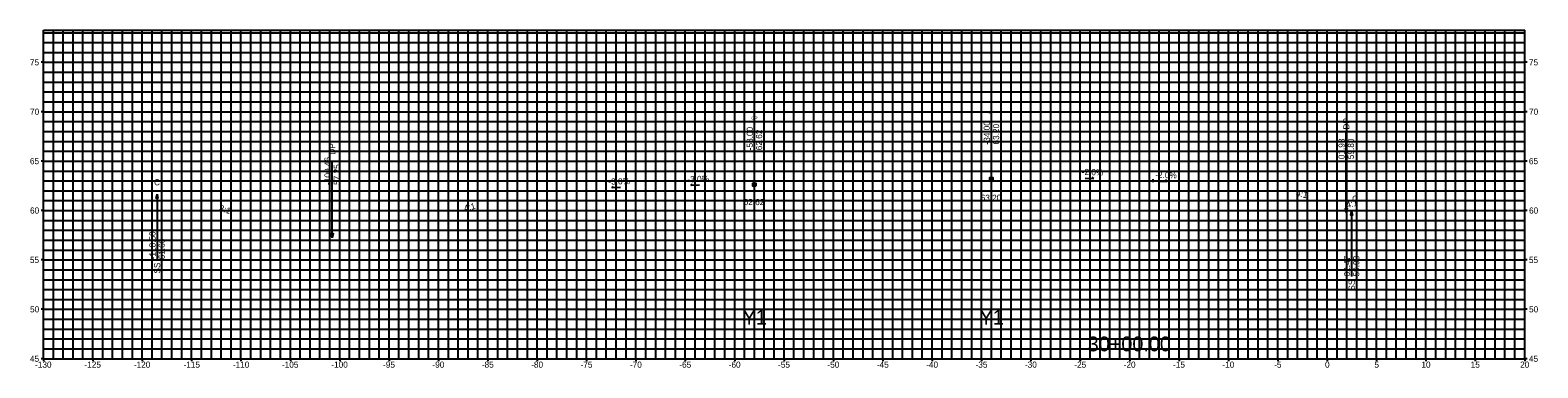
# Model space of a CAD drawing. Extents: x -111 to 41, y 44 to 78.
import ezdxf

# ---------------------------------------------------------------- set-up
doc = ezdxf.new("R2010")
doc.units = 0
for name, color, linetype in [('P_NCDOT_XS_Label_Grade_Point', 7, 'Continuous'), ('P_NCDOT_XS_Label_Grading_Side_Slope', 7, 'Continuous'), ('P_NCDOT_XS_Leader_Line', 7, 'Continuous'), ('P_NCDOT_XS_Sheet_Alignment_Station_Label', 7, 'Continuous'), ('P_NCDOT_XS_Sheet_Grid_Border', 7, 'Continuous'), ('P_NCDOT_XS_Slope_Label', 7, 'Continuous'), ('Sheet_Cross_Section_Scale_CELL', 7, 'Continuous'), ('Sheet_Grid_Middle', 7, 'Continuous'), ('Sheet_Grid_Minor', 7, 'Continuous'), ('Sheet_Named_Boundary', 7, 'Continuous'), ('Sheet_Plan_CELL', 7, 'Continuous'), ('Sheet_RDY_XS_Number', 7, 'Continuous'), ('Sheet_RDY_XS_Project_Number', 7, 'Continuous'), ('z - Construction', 7, 'Continuous')]:
    doc.layers.add(name, color=color, linetype=linetype)

msp = doc.modelspace()

# ---------------------------------------------------------------- linework, layer by layer
at = {"layer": 'P_NCDOT_XS_Label_Grading_Side_Slope'}
for p, q in [((-44.45, 62.54), (-44.28, 62.67)), ((-4.52, 63.27), (-3.62, 63.25)), ((-3.62, 63.25), (-3.79, 63.38)), ((2.91, 62.98), (3.81, 62.96)), ((3.81, 62.96), (3.64, 63.08)), ((-52.45, 62.3), (-52.28, 62.43)), ((-51.55, 62.33), (-52.45, 62.3)), ((-43.55, 62.57), (-44.45, 62.54))]:
    msp.add_line(p, q, dxfattribs=at)
at = {"layer": 'P_NCDOT_XS_Sheet_Alignment_Station_Label'}
for p, q in [((-38, 62.62), (-38, 68.86)), ((-14, 63.2), (-14, 69.44)), ((21.93, 59.8), (21.93, 67.9)), ((21.93, 59.8), (21.93, 67.6)), ((-80.76, 57.25), (-80.76, 65.05)), ((-98.5, 61.66), (-98.5, 55.06)), ((22.47, 59.93), (22.47, 53.33))]:
    msp.add_line(p, q, dxfattribs=at)
for points in [[(-37.85, 62.47), (-38.15, 62.47), (-38.15, 62.77), (-37.85, 62.77)], [(-13.85, 63.05), (-14.15, 63.05), (-14.15, 63.35), (-13.85, 63.35)], [(-98.5, 61.66), (-98.41, 61.25), (-98.58, 61.25)], [(21.93, 59.8), (21.84, 60.21), (22.01, 60.21)], [(21.93, 59.8), (21.85, 60.21), (22.02, 60.21)], [(22.47, 59.93), (22.56, 59.52), (22.39, 59.52)], [(-80.76, 57.25), (-80.85, 57.66), (-80.67, 57.66)]]:
    msp.add_lwpolyline(points, close=True, dxfattribs=at)
at = {"layer": 'Sheet_Grid_Middle'}
for p, q in [((2.36, 62.87), (2.36, 63.18)), ((-50, 62.26), (-50, 62.57))]:
    msp.add_line(p, q, dxfattribs=at)
at = {"layer": 'Sheet_Named_Boundary'}
for p, q in [((-110, 78.26), (40, 78.26)), ((-110, 45), (-110, 78.26)), ((40, 45), (40, 78.26)), ((-110, 45), (40, 45))]:
    msp.add_line(p, q, dxfattribs=at)
at = {"layer": 'Sheet_Plan_CELL'}
for p, q in [((-110, 78), (40, 78)), ((-109, 45), (-109, 78.26)), ((-108, 45), (-108, 78.26)), ((-107, 45), (-107, 78.26)), ((-106, 45), (-106, 78.26)), ((-104, 45), (-104, 78.26)), ((-103, 45), (-103, 78.26)), ((-102, 45), (-102, 78.26)), ((-101, 45), (-101, 78.26)), ((-99, 45), (-99, 78.26)), ((-98, 45), (-98, 78.26)), ((-97, 45), (-97, 78.26)), ((-96, 45), (-96, 78.26)), ((-94, 45), (-94, 78.26)), ((-93, 45), (-93, 78.26)), ((-92, 45), (-92, 78.26)), ((-91, 45), (-91, 78.26)), ((-89, 45), (-89, 78.26)), ((-88, 45), (-88, 78.26)), ((-87, 45), (-87, 78.26)), ((-86, 45), (-86, 78.26)), ((-84, 45), (-84, 78.26)), ((-83, 45), (-83, 78.26)), ((-82, 45), (-82, 78.26)), ((-81, 45), (-81, 78.26)), ((-79, 45), (-79, 78.26)), ((-78, 45), (-78, 78.26)), ((-77, 45), (-77, 78.26)), ((-76, 45), (-76, 78.26)), ((-74, 45), (-74, 78.26)), ((-73, 45), (-73, 78.26)), ((-72, 45), (-72, 78.26)), ((-71, 45), (-71, 78.26)), ((-69, 45), (-69, 78.26)), ((-68, 45), (-68, 78.26)), ((-67, 45), (-67, 78.26)), ((-66, 45), (-66, 78.26)), ((-64, 45), (-64, 78.26)), ((-63, 45), (-63, 78.26)), ((-62, 45), (-62, 78.26)), ((-61, 45), (-61, 78.26)), ((-59, 45), (-59, 78.26)), ((-58, 45), (-58, 78.26)), ((-57, 45), (-57, 78.26)), ((-56, 45), (-56, 78.26)), ((-54, 45), (-54, 78.26)), ((-53, 45), (-53, 78.26)), ((-52, 45), (-52, 78.26)), ((-51, 45), (-51, 78.26)), ((-49, 45), (-49, 78.26)), ((-48, 45), (-48, 78.26)), ((-47, 45), (-47, 78.26)), ((-46, 45), (-46, 78.26)), ((-44, 45), (-44, 78.26)), ((-43, 45), (-43, 78.26)), ((-42, 45), (-42, 78.26)), ((-41, 45), (-41, 78.26)), ((-39, 45), (-39, 78.26)), ((-38, 45), (-38, 78.26)), ((-37, 45), (-37, 78.26)), ((-36, 45), (-36, 78.26)), ((-34, 45), (-34, 78.26)), ((-33, 45), (-33, 78.26)), ((-32, 45), (-32, 78.26)), ((-31, 45), (-31, 78.26)), ((-29, 45), (-29, 78.26)), ((-28, 45), (-28, 78.26)), ((-27, 45), (-27, 78.26)), ((-26, 45), (-26, 78.26)), ((-24, 45), (-24, 78.26)), ((-23, 45), (-23, 78.26)), ((-22, 45), (-22, 78.26)), ((-21, 45), (-21, 78.26)), ((-19, 45), (-19, 78.26)), ((-18, 45), (-18, 78.26)), ((-17, 45), (-17, 78.26)), ((-16, 45), (-16, 78.26)), ((-14, 45), (-14, 78.26)), ((-13, 45), (-13, 78.26)), ((-12, 45), (-12, 78.26)), ((-11, 45), (-11, 78.26)), ((-9, 45), (-9, 78.26)), ((-8, 45), (-8, 78.26)), ((-7, 45), (-7, 78.26)), ((-6, 45), (-6, 78.26)), ((-4, 45), (-4, 78.26)), ((-3, 45), (-3, 78.26)), ((-2, 45), (-2, 78.26)), ((-1, 45), (-1, 78.26)), ((1, 45), (1, 78.26)), ((2, 45), (2, 78.26)), ((3, 45), (3, 78.26)), ((4, 45), (4, 78.26)), ((6, 45), (6, 78.26)), ((7, 45), (7, 78.26)), ((8, 45), (8, 78.26)), ((9, 45), (9, 78.26)), ((11, 45), (11, 78.26)), ((12, 45), (12, 78.26)), ((13, 45), (13, 78.26)), ((14, 45), (14, 78.26)), ((16, 45), (16, 78.26)), ((17, 45), (17, 78.26)), ((18, 45), (18, 78.26)), ((19, 45), (19, 78.26)), ((21, 45), (21, 78.26)), ((22, 45), (22, 78.26)), ((23, 45), (23, 78.26)), ((24, 45), (24, 78.26)), ((26, 45), (26, 78.26)), ((27, 45), (27, 78.26)), ((28, 45), (28, 78.26)), ((29, 45), (29, 78.26)), ((31, 45), (31, 78.26)), ((32, 45), (32, 78.26)), ((33, 45), (33, 78.26)), ((34, 45), (34, 78.26)), ((36, 45), (36, 78.26)), ((37, 45), (37, 78.26)), ((38, 45), (38, 78.26)), ((39, 45), (39, 78.26)), ((-110, 77), (40, 77)), ((-110, 76), (40, 76)), ((-110, 74), (40, 74)), ((-110, 73), (40, 73)), ((-110, 72), (40, 72)), ((-110, 71), (40, 71)), ((-110, 69), (40, 69)), ((-110, 68), (40, 68)), ((-110, 67), (40, 67)), ((-110, 66), (40, 66)), ((-110, 64), (40, 64)), ((-110, 63), (40, 63)), ((-110, 62), (40, 62)), ((-110, 61), (40, 61)), ((-110, 59), (40, 59)), ((-110, 58), (40, 58)), ((-110, 57), (40, 57)), ((-110, 56), (40, 56)), ((-110, 54), (40, 54)), ((-110, 53), (40, 53)), ((-110, 52), (40, 52)), ((-110, 51), (40, 51)), ((-110, 49), (40, 49)), ((-110, 48), (40, 48)), ((-110, 47), (40, 47)), ((-110, 46), (40, 46))]:
    msp.add_line(p, q, dxfattribs=at)
at = {"layer": 'Sheet_RDY_XS_Number'}
for p, q in [((-105, 45), (-105, 78.26)), ((-100, 45), (-100, 78.26)), ((-95, 45), (-95, 78.26)), ((-90, 45), (-90, 78.26)), ((-85, 45), (-85, 78.26)), ((-80, 45), (-80, 78.26)), ((-75, 45), (-75, 78.26)), ((-70, 45), (-70, 78.26)), ((-65, 45), (-65, 78.26)), ((-60, 45), (-60, 78.26)), ((-55, 45), (-55, 78.26)), ((-50, 45), (-50, 78.26)), ((-45, 45), (-45, 78.26)), ((-40, 45), (-40, 78.26)), ((-35, 45), (-35, 78.26)), ((-30, 45), (-30, 78.26)), ((-25, 45), (-25, 78.26)), ((-20, 45), (-20, 78.26)), ((-15, 45), (-15, 78.26)), ((-10, 45), (-10, 78.26)), ((-5, 45), (-5, 78.26)), ((0, 45), (0, 78.26)), ((5, 45), (5, 78.26)), ((10, 45), (10, 78.26)), ((15, 45), (15, 78.26)), ((20, 45), (20, 78.26)), ((25, 45), (25, 78.26)), ((30, 45), (30, 78.26)), ((35, 45), (35, 78.26)), ((-110, 75), (-110.24, 75)), ((-110, 75), (40, 75)), ((40.24, 75), (40, 75)), ((-110, 70), (-110.24, 70)), ((-110, 70), (40, 70)), ((40.24, 70), (40, 70)), ((-110, 65), (-110.24, 65)), ((-110, 65), (40, 65)), ((40.24, 65), (40, 65)), ((-110, 60), (-110.24, 60)), ((-110, 60), (40, 60)), ((40.24, 60), (40, 60)), ((-110, 55), (-110.24, 55)), ((-110, 55), (40, 55)), ((40.24, 55), (40, 55)), ((-110, 50), (-110.24, 50)), ((-110, 50), (40, 50)), ((40.24, 50), (40, 50)), ((-110, 45), (-110.24, 45)), ((-110, 45), (-110, 44.76)), ((-105, 45), (-105, 44.76)), ((-100, 45), (-100, 44.76)), ((-95, 45), (-95, 44.76)), ((-90, 45), (-90, 44.76)), ((-85, 45), (-85, 44.76)), ((-80, 45), (-80, 44.76)), ((-75, 45), (-75, 44.76)), ((-70, 45), (-70, 44.76)), ((-65, 45), (-65, 44.76)), ((-60, 45), (-60, 44.76)), ((-55, 45), (-55, 44.76)), ((-50, 45), (-50, 44.76)), ((-45, 45), (-45, 44.76)), ((-40, 45), (-40, 44.76)), ((-35, 45), (-35, 44.76)), ((-30, 45), (-30, 44.76)), ((-25, 45), (-25, 44.76)), ((-20, 45), (-20, 44.76)), ((-15, 45), (-15, 44.76)), ((-10, 45), (-10, 44.76)), ((-5, 45), (-5, 44.76)), ((0, 45), (0, 44.76)), ((5, 45), (5, 44.76)), ((10, 45), (10, 44.76)), ((15, 45), (15, 44.76)), ((20, 45), (20, 44.76)), ((25, 45), (25, 44.76)), ((30, 45), (30, 44.76)), ((35, 45), (35, 44.76)), ((40, 45), (40, 44.76)), ((40.24, 45), (40, 45))]:
    msp.add_line(p, q, dxfattribs=at)
at = {"layer": 'Sheet_RDY_XS_Project_Number'}
for p, q in [((-100, 45), (-100, 78.26)), ((-90, 45), (-90, 78.26)), ((-80, 45), (-80, 78.26)), ((-70, 45), (-70, 78.26)), ((-60, 45), (-60, 78.26)), ((-50, 45), (-50, 78.26)), ((-40, 45), (-40, 78.26)), ((-30, 45), (-30, 78.26)), ((-20, 45), (-20, 78.26)), ((-10, 45), (-10, 78.26)), ((0, 45), (0, 78.26)), ((10, 45), (10, 78.26)), ((20, 45), (20, 78.26)), ((30, 45), (30, 78.26)), ((-110, 70), (40, 70)), ((-110, 60), (40, 60)), ((-110, 50), (40, 50))]:
    msp.add_line(p, q, dxfattribs=at)

# ---------------------------------------------------------------- texts
at = {"layer": 'P_NCDOT_XS_Label_Grade_Point'}
for s, p in [('DP', (22.25, 68.2)), ('01.93', (21.77, 65.2)), ('59.80', (22.71, 65.2)), ('DP', (-80.45, 65.65)), ('-100.46', (-80.92, 62.59)), ('57.25', (-79.98, 62.59)), ('-118.50', (-98.65, 55.06)), ('61.66', (-97.72, 55.06)), ('02.47', (22.32, 53.33)), ('59.93', (23.25, 53.33)), ('SS', (-98.18, 53.62)), ('SS', (22.79, 51.89))]:
    msp.add_text(s, height=0.624, rotation=90, dxfattribs=at).set_placement(p)
for p in [(-98.8, 62.55), (22.52, 60.88)]:
    msp.add_text('C', height=0.624, dxfattribs=at).set_placement(p)
at = {"layer": 'P_NCDOT_XS_Leader_Line'}
for p in [(-38.31, 69.19), (-14.31, 69.77)]:
    msp.add_text('GP', height=0.312, dxfattribs=at).set_placement(p)
for s, p in [('-34.00', (-14.16, 66.68)), ('63.20', (-13.22, 66.68)), ('-58.00', (-38.16, 66.1)), ('62.62', (-37.22, 66.1))]:
    msp.add_text(s, height=0.624, rotation=90, dxfattribs=at).set_placement(p)
at = {"layer": 'P_NCDOT_XS_Sheet_Grid_Border'}
for s, p in [('62.62', (-39.09, 60.55)), ('63.20', (-15.09, 60.98))]:
    msp.add_text(s, height=0.624, dxfattribs=at).set_placement(p)
at = {"layer": 'P_NCDOT_XS_Slope_Label'}
for s, rotation, p in [('-2.0%', 358.8542, (-4.86, 63.6)), ('-3.0%', 1.7184, (-52.78, 62.61)), ('-2.0%', 358.8542, (2.58, 63.3)), ('4:1', 345.9638, (16.8, 61.51)), ('4:1', 14.0362, (22.01, 60.24)), ('3:1', 341.5668, (-92.26, 60)), ('4:1', 14.0362, (-67.33, 59.91))]:
    msp.add_text(s, height=0.624, rotation=rotation, dxfattribs=at).set_placement(p)
at = {"layer": 'Sheet_Cross_Section_Scale_CELL'}
for s, p in [('Y1', (-39.2, 48.45)), ('Y1', (-15.2, 48.45)), ('30+00.00', (-4.25, 45.75))]:
    msp.add_text(s, height=1.5, dxfattribs=at).set_placement(p)
at = {"layer": 'Sheet_Grid_Minor'}
msp.add_text('-3.0%', height=0.624, rotation=1.7184, dxfattribs=at).set_placement((-44.78, 62.85))
at = {"layer": 'z - Construction'}
for s, p in [('75', (-111.37, 74.69)), ('75', (40.43, 74.69)), ('70', (-111.36, 69.69)), ('70', (40.44, 69.69)), ('65', (-111.37, 64.69)), ('65', (40.43, 64.69)), ('60', (-111.36, 59.69)), ('60', (40.44, 59.69)), ('55', (-111.37, 54.69)), ('55', (40.43, 54.69)), ('50', (-111.36, 49.69)), ('50', (40.44, 49.69)), ('45', (-111.37, 44.69)), ('-130', (-110.85, 44.09)), ('-125', (-105.85, 44.09)), ('-120', (-100.85, 44.09)), ('-115', (-95.82, 44.09)), ('-110', (-90.82, 44.09)), ('-105', (-85.85, 44.09)), ('-100', (-80.85, 44.09)), ('-95', (-75.61, 44.09)), ('-90', (-70.61, 44.09)), ('-85', (-65.61, 44.09)), ('-80', (-60.61, 44.09)), ('-75', (-55.61, 44.09)), ('-70', (-50.61, 44.09)), ('-65', (-45.61, 44.09)), ('-60', (-40.61, 44.09)), ('-55', (-35.61, 44.09)), ('-50', (-30.61, 44.09)), ('-45', (-25.61, 44.09)), ('-40', (-20.61, 44.09)), ('-35', (-15.61, 44.09)), ('-30', (-10.61, 44.09)), ('-25', (-5.61, 44.09)), ('-20', (-0.61, 44.09)), ('-15', (4.39, 44.09)), ('-10', (9.39, 44.09)), ('-5', (14.63, 44.09)), ('0', (19.78, 44.09)), ('5', (24.78, 44.09)), ('10', (29.54, 44.09)), ('15', (34.53, 44.09)), ('20', (39.54, 44.09)), ('45', (40.43, 44.69))]:
    msp.add_text(s, height=0.624, dxfattribs=at).set_placement(p)

doc.saveas('drawing.dxf')
